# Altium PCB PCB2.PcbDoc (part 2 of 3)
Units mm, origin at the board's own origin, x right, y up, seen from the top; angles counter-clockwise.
Board outline 277.37 x 238.38 mm, 2 copper layers (Top Layer, Bottom Layer); 139 components, 149 nets, 593 pads, 86 vias.
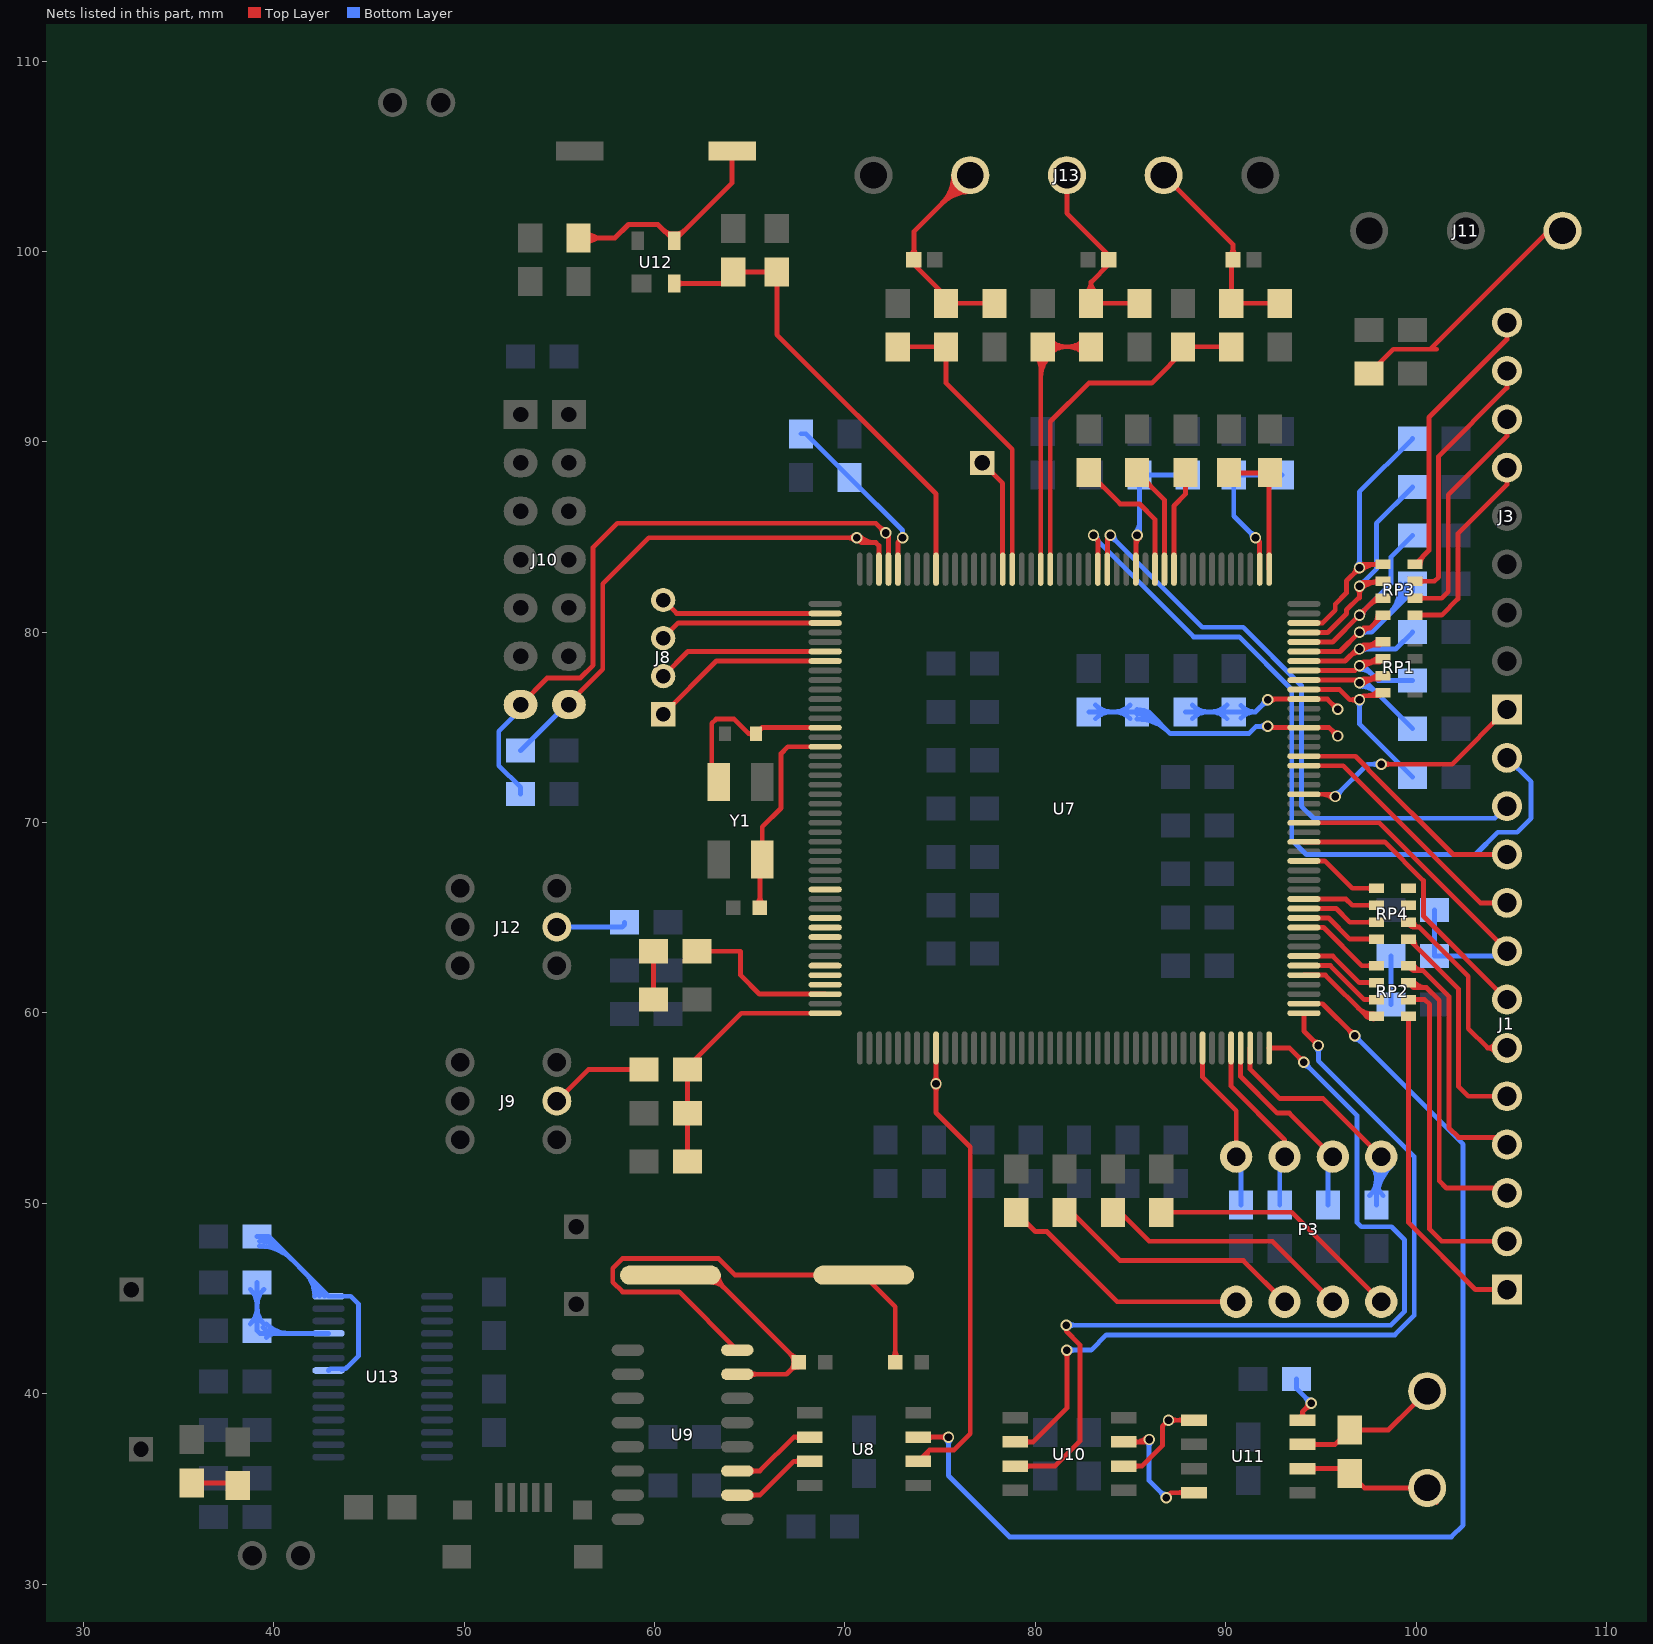
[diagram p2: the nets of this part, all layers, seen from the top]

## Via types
v1: diameter 0.6, hole 0.4, Top Layer to Bottom Layer, 86 vias

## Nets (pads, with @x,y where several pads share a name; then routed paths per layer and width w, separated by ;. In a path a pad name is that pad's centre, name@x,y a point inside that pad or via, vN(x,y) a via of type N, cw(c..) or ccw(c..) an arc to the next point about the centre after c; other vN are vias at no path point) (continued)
A0: C32.2 RP3.5 U7.42 | length 19.1
  Top Layer w0.254: U7.42@94.109,80.489 95.094,80.489 95.758,81.153 95.758,81.481 96.347,82.07 96.347,82.705 96.954,83.312 v1@97.028,83.312 ; v1(97.028,83.386) 97.208,83.566 RP3.5@98.26,83.566 ; 96.733,83.091 cw(c97.028,82.795) 97.028,83.213 ccw(c97.028,82.795) 96.733,83.091 ; 96.733,83.091 ccw(c96.437,83.386) 96.855,83.386 cw(c96.437,83.386) 96.733,83.091 ; 97.813,83.566 cw(c97.813,83.269) 98.023,83.479 ccw(c97.813,83.269) 97.813,83.566 ; 97.813,83.566 ccw(c97.813,83.863) 98.023,83.653 cw(c97.813,83.863) 97.813,83.566 ; v1@97.15,83.264 cw(c97.88,82.534) 97.88,83.566 ccw(c97.88,82.534) v1@97.15,83.264
  Bottom Layer w0.254: v1(97.028,83.386) 97.028,87.376 C32.2@99.822,90.17 ; 97.028,83.804 cw(c96.61,83.804) 96.906,83.508 ccw(c96.61,83.804) 97.028,83.804 ; 97.028,83.804 ccw(c97.446,83.804) 97.15,83.508 cw(c97.446,83.804) 97.028,83.804
A1: C31.2 RP3.6 U7.41 | length 18.3
  Top Layer w0.254: U7.41@94.109,79.989 95.356,79.989 96.347,80.98 96.347,81.181 96.954,81.788 97.028,81.788 v1(97.028,82.423) 97.236,82.631 RP3.6@98.214,82.631 ; RP3.6@97.956,82.631 RP3.6@98.214,82.631 ; RP3.6@98.26,82.677 RP3.6@98.214,82.631 ; 97.028,82.005 cw(c97.446,82.005) v1@97.15,82.301 ; 97.028,82.005 ccw(c96.61,82.005) 96.906,82.301 cw(c96.61,82.005) 97.028,82.005 ; 97.028,82.005 cw(c97.446,82.005) v1@97.15,82.301 ; v1@97.15,82.301 cw(c97.948,81.503) 97.948,82.631 ccw(c97.948,81.503) v1@97.15,82.301 ; v1@96.971,82.48 cw(c97.335,82.116) 97.335,82.631 ccw(c97.335,82.116) v1@96.971,82.48 ; 97.702,82.631 ccw(c97.702,83.085) 98.023,82.764 cw(c97.702,83.085) 97.702,82.631
  Bottom Layer w0.254: v1(97.028,82.423) 97.917,83.312 97.917,85.725 C31.2@99.822,87.63 ; 97.323,82.718 cw(c97.028,83.014) 97.028,82.596 ccw(c97.028,83.014) 97.323,82.718 ; 97.323,82.718 ccw(c97.619,82.423) 97.201,82.423 cw(c97.619,82.423) 97.323,82.718
A2: C30.2 RP3.7 U7.40 | length 14.3
  Top Layer w0.254: U7.40@94.109,79.489 95.618,79.489 v1(97.028,80.899) 97.917,81.788 RP3.7@98.26,81.788 ; 97.323,81.194 cw(c97.028,81.49) 97.028,81.072 ccw(c97.028,81.49) 97.323,81.194 ; 97.323,81.194 ccw(c97.619,80.899) 97.201,80.899 cw(c97.619,80.899) 97.323,81.194 ; 97.571,81.442 cw(c98.11,80.902) 98.11,81.665 ccw(c98.11,80.902) 97.571,81.442
  Bottom Layer w0.254: v1(97.028,80.899) 98.679,82.55 98.679,83.947 C30.2@99.822,85.09 ; 97.323,81.194 cw(c97.028,81.49) 97.028,81.072 ccw(c97.028,81.49) 97.323,81.194 ; 97.323,81.194 ccw(c97.619,80.899) 97.201,80.899 cw(c97.619,80.899) 97.323,81.194
A3: C29.2 RP3.8 U7.39 | length 21
  Top Layer w0.254: U7.39@94.109,78.989 96.007,78.989 v1(97.028,80.01) 97.236,80.218 97.579,80.218 ; RP3.8@98.26,80.899 97.579,80.218 ; 97.579,80.218 ccw(c97.579,79.802) 97.19,79.949 cw(c97.579,79.802) 97.579,80.218 ; 97.794,80.433 ccw(c97.328,80.899) 97.987,80.899 cw(c97.328,80.899) 97.794,80.433
  Bottom Layer w0.254: v1(97.028,80.01) 97.663,80.01 99.822,82.169 C29.2@99.822,82.55 ; 97.446,80.01 cw(c97.446,80.428) 97.15,80.132 ccw(c97.446,80.428) 97.446,80.01 ; 97.446,80.01 ccw(c97.446,79.592) 97.15,79.888 cw(c97.446,79.592) 97.446,80.01 ; 98.469,80.816 ccw(c96.734,82.55) 99.187,82.55 cw(c96.734,82.55) 98.469,80.816 ; 98.902,81.249 ccw(c97.601,82.55) 99.441,82.55 cw(c97.601,82.55) 98.902,81.249 ; 99.336,81.683 ccw(c98.469,82.55) 99.695,82.55 cw(c98.469,82.55) 99.336,81.683
A4: C28.2 RP1.5 U7.38 | length 14.2
  Top Layer w0.254: U7.38@94.109,78.489 96.269,78.489 96.901,79.121 v1(97.028,79.121) 97.236,79.329 98.087,79.329 RP1.5@98.26,79.502 ; 96.516,78.736 cw(c97.028,78.224) 97.028,78.948 ccw(c97.028,78.224) 96.516,78.736 ; v1@96.971,79.178 cw(c97.335,78.814) 97.335,79.329 ccw(c97.335,78.814) v1@96.971,79.178 ; v1@97.15,78.999 cw(c97.948,78.201) 97.948,79.329 ccw(c97.948,78.201) v1@97.15,78.999 ; 97.395,79.329 ccw(c97.395,80.217) 98.023,79.589 cw(c97.395,80.217) 97.395,79.329
  Bottom Layer w0.254: v1(97.028,79.121) 98.933,79.121 C28.2@99.822,80.01 ; 97.446,79.121 cw(c97.446,79.539) 97.15,79.243 ccw(c97.446,79.539) 97.446,79.121 ; 97.446,79.121 ccw(c97.446,78.703) 97.15,78.999 cw(c97.446,78.703) 97.446,79.121
A5: C27.1 RP1.6 U7.37 | length 12.3
  Top Layer w0.254: U7.37@94.109,77.989 96.785,77.989 ; v1@97.236,78.44 98.087,78.44 RP1.6@98.26,78.613 ; v1@96.971,78.289 cw(c97.335,77.925) 97.335,78.44 ccw(c97.335,77.925) v1@96.971,78.289 ; v1@97.15,78.11 cw(c97.948,77.312) 97.948,78.44 ccw(c97.948,77.312) v1@97.15,78.11 ; 97.395,78.44 ccw(c97.395,79.328) 98.023,78.7 cw(c97.395,79.328) 97.395,78.44
  Bottom Layer w0.254: v1(97.028,78.232) 97.238,78.232 98,77.47 C27.1@99.822,77.47 ; v1@97.028,78.059 cw(c97.028,77.133) 97.683,77.788 ccw(c97.028,77.133) v1@97.028,78.059
A6: C26.2 RP1.7 U7.36 | length 15.2
  Top Layer w0.254: U7.36@94.109,77.489 v1@96.882,77.489 ; v1(97.028,77.343) 97.236,77.551 98.087,77.551 RP1.7@98.26,77.724 ; v1@96.971,77.4 cw(c97.335,77.036) 97.335,77.551 ccw(c97.335,77.036) v1@96.971,77.4 ; v1@97.15,77.221 cw(c97.948,76.423) 97.948,77.551 ccw(c97.948,76.423) v1@97.15,77.221 ; 97.395,77.551 ccw(c97.395,78.439) 98.023,77.811 cw(c97.395,78.439) 97.395,77.551
  Bottom Layer w0.254: v1(97.028,77.343) 97.409,77.343 C26.2@99.822,74.93 ; v1@97.028,77.17 cw(c97.028,75.833) 97.974,76.778 ccw(c97.028,75.833) v1@97.028,77.17 ; v1@97.028,77.424 cw(c97.028,76.7) 97.54,77.212 ccw(c97.028,76.7) v1@97.028,77.424
A7: C25.2 RP1.8 U7.35 | length 13.8
  Top Layer w0.254: U7.35@94.109,76.989 95.985,76.989 96.52,76.454 v1(97.028,76.454) 97.236,76.662 98.087,76.662 RP1.8@98.26,76.835 ; 96.61,76.454 cw(c96.61,76.036) 96.906,76.332 ccw(c96.61,76.036) 96.61,76.454 ; 96.61,76.454 ccw(c96.61,76.872) 96.906,76.576 cw(c96.61,76.872) 96.61,76.454 ; 97.395,76.662 ccw(c97.395,77.55) 98.023,76.922 cw(c97.395,77.55) 97.395,76.662
  Bottom Layer w0.254: v1(97.028,76.454) 97.028,75.184 C25.2@99.822,72.39 ; 97.028,76.036 cw(c97.446,76.036) 97.15,76.332 ccw(c97.446,76.036) 97.028,76.036 ; 97.028,76.036 ccw(c96.61,76.036) 96.906,76.332 cw(c96.61,76.036) 97.028,76.036
A_FB: J3.7 RP3.2 | length 13.1
  Top Layer w0.254: RP3.2@99.949,81.788 101.346,81.788 101.693,82.135 101.693,87.216 104.775,90.298 J3.7@104.775,91.186 ; 100.396,81.788 cw(c100.396,82.085) 100.186,81.875 ccw(c100.396,82.085) 100.396,81.788 ; 100.396,81.788 ccw(c100.396,81.491) 100.186,81.701 cw(c100.396,81.491) 100.396,81.788
B0: C33.2 R23.2 U7.46 | length 9.4
  Top Layer w0.254: v1(91.567,84.963) 91.784,84.746 U7.46@91.784,83.314
  Bottom Layer w0.254: v1(91.567,84.963) 90.424,86.106 R23.2@90.424,88.265 C33.2@92.964,88.265 ; 91.272,85.258 cw(c90.976,84.963) 91.394,84.963 ccw(c90.976,84.963) 91.272,85.258 ; 91.272,85.258 ccw(c91.567,85.554) 91.567,85.136 cw(c91.567,85.554) 91.272,85.258
B_FB: J3.8 RP3.3 | length 14.6
  Top Layer w0.254: RP3.3@99.949,82.677 100.965,82.677 101.185,82.897 101.185,89.248 104.775,92.838 J3.8@104.775,93.726 ; 100.396,82.677 cw(c100.396,82.974) 100.186,82.764 ccw(c100.396,82.974) 100.396,82.677 ; 100.396,82.677 ccw(c100.396,82.38) 100.186,82.59 cw(c100.396,82.38) 100.396,82.677
C_FB: J3.9 RP3.4 | length 15.7
  Top Layer w0.254: RP3.4@99.949,83.566 100.677,84.294 100.677,91.28 104.775,95.378 J3.9@104.775,96.266 ; RP3.4@100.222,83.566 cw(c100.881,83.566) 100.415,84.032 ccw(c100.881,83.566) RP3.4@100.222,83.566
CANRXA: U7.1 U10.2 | length 50.4
  Top Layer w0.254: U10.2@78.938,37.465 79.883,37.465 81.661,39.243 v1(81.661,42.291) ; U7.1@94.109,59.989 94.109,59.053 v1(94.869,58.293) ; 79.731,37.465 cw(c79.731,37.883) 79.435,37.587 ccw(c79.731,37.883) 79.731,37.465 ; 79.731,37.465 ccw(c79.731,37.047) 79.435,37.343 cw(c79.731,37.047) 79.731,37.465 ; 81.661,41.873 cw(c82.079,41.873) 81.783,42.169 ccw(c82.079,41.873) 81.661,41.873 ; 81.661,41.873 ccw(c81.243,41.873) 81.539,42.169 cw(c81.243,41.873) 81.661,41.873 ; 94.574,58.588 cw(c94.278,58.293) 94.696,58.293 ccw(c94.278,58.293) 94.574,58.588 ; 94.574,58.588 ccw(c94.869,58.884) 94.869,58.466 cw(c94.869,58.884) 94.574,58.588
  Bottom Layer w0.254: v1(81.661,42.291) 82.931,42.291 83.732,43.092 98.891,43.092 99.91,44.111 99.91,52.453 94.869,57.494 v1(94.869,58.293) ; 82.079,42.291 cw(c82.079,42.709) 81.783,42.413 ccw(c82.079,42.709) 82.079,42.291 ; 82.079,42.291 ccw(c82.079,41.873) 81.783,42.169 cw(c82.079,41.873) 82.079,42.291 ; 94.869,57.875 cw(c95.287,57.875) 94.991,58.171 ccw(c95.287,57.875) 94.869,57.875 ; 94.869,57.875 ccw(c94.451,57.875) 94.747,58.171 cw(c94.451,57.875) 94.869,57.875
CANTXA: U7.176 U10.3 | length 52
  Top Layer w0.254: U10.3@78.938,36.195 81.026,36.195 82.342,37.511 82.342,42.573 81.622,43.293 v1(81.622,43.6) ; U7.176@92.284,58.164 93.347,58.164 v1(94.107,57.404) ; 79.731,36.195 cw(c79.731,36.613) 79.435,36.317 ccw(c79.731,36.613) 79.731,36.195 ; 79.731,36.195 ccw(c79.731,35.777) 79.435,36.073 cw(c79.731,35.777) 79.731,36.195 ; 93.812,57.699 cw(c93.516,57.404) 93.934,57.404 ccw(c93.516,57.404) 93.812,57.699 ; 93.812,57.699 ccw(c94.107,57.995) 94.107,57.577 cw(c94.107,57.995) 93.812,57.699
  Bottom Layer w0.254: v1(81.622,43.6) 98.681,43.6 99.402,44.321 99.402,48.076 98.71,48.768 97.124,48.768 96.901,48.991 96.901,54.61 v1(94.107,57.404) ; 82.04,43.6 cw(c82.04,44.018) 81.744,43.722 ccw(c82.04,44.018) 82.04,43.6 ; 82.04,43.6 ccw(c82.04,43.182) 81.744,43.478 cw(c82.04,43.182) 82.04,43.6 ; 94.402,57.109 cw(c94.698,57.404) 94.28,57.404 ccw(c94.698,57.404) 94.402,57.109 ; 94.402,57.109 ccw(c94.107,56.813) 94.107,57.231 cw(c94.107,56.813) 94.402,57.109
DC_FB: J3.6 RP3.1 | length 11.5
  Top Layer w0.254: RP3.1@99.949,80.899 101.346,80.899 102.201,81.754 102.201,85.184 104.775,87.758 J3.6@104.775,88.646 ; 100.396,80.899 cw(c100.396,81.196) 100.186,80.986 ccw(c100.396,81.196) 100.396,80.899 ; 100.396,80.899 ccw(c100.396,80.602) 100.186,80.812 cw(c100.396,80.602) 100.396,80.899
DIR: C49.2 R27.2 R33.2 U7.132 | length 13.4
  Top Layer w0.254: C49.2@61.722,52.197 R33.2@61.722,54.737 R27.2@61.722,57.023 61.722,57.15 64.561,59.989 U7.132@68.959,59.989
EMU0: J10.13 R36.2 U7.85 | length 35.7
  Top Layer w0.254: J10.13@52.959,76.2 54.356,77.597 56.099,77.597 56.769,78.267 56.769,84.455 58.039,85.725 71.628,85.725 v1(72.136,85.217) ; U7.85@72.284,83.314 v1@72.284,85.069 ; 71.841,85.512 cw(c71.545,85.217) 71.963,85.217 ccw(c71.545,85.217) 71.841,85.512 ; 71.841,85.512 ccw(c72.136,85.808) 72.136,85.39 cw(c72.136,85.808) 71.841,85.512
  Bottom Layer w0.254: R36.2@52.959,71.501 52.959,71.851 51.816,72.994 51.816,74.803 52.959,75.946 J10.13@52.959,76.2
EMU1: J10.14 R37.1 U7.86 | length 31.8
  Top Layer w0.254: J10.14@55.499,76.2 55.499,76.278 57.277,78.056 57.277,82.55 59.69,84.963 v1(70.612,84.963) 70.866,84.709 71.628,84.709 ; U7.86@71.784,83.314 71.784,84.553 71.628,84.709 ; 70.194,84.963 cw(c70.194,84.545) 70.49,84.841 ccw(c70.194,84.545) 70.194,84.963 ; 70.194,84.963 ccw(c70.194,85.381) 70.49,85.085 cw(c70.194,85.381) 70.194,84.963 ; 71.628,84.709 cw(c71.628,85.958) 70.736,85.084 ccw(c71.628,85.958) 71.628,84.709 ; v1@70.554,84.906 ccw(c71.024,85.366) 71.024,84.709 cw(c71.024,85.366) v1@70.554,84.906
  Bottom Layer w0.254: R37.1@52.959,73.787 J10.14@55.372,76.2
EN_GATE: J1.7 U7.19 | length 15.2
  Top Layer w0.254: U7.19@94.109,68.989 98.354,68.989 100.387,66.956 100.387,65.094 J1.7@104.775,60.706
GHA: 
GHB: 
GHC: 
GLA: 
GLB: 
GLC: 
GPIO66: U7.119
GPIO67: U7.122
GPIO68: U7.123
GPIO69: U7.124
GPIO70: U7.127
GPIO71: U7.128
GPIO72: U7.129
GPIO84: P3.1 R38.2 U7.169 | length 8.7
  Top Layer w0.254: U7.169@88.784,58.164 88.784,56.631 90.551,54.864 P3.1@90.551,52.451
  Bottom Layer w0.254: R38.2@90.805,49.911 P3.1@90.805,52.197
GPIO85: P3.2 R39.2 U7.172 | length 9.2
  Top Layer w0.254: U7.172@90.284,58.164 90.284,56.147 93.091,53.34 P3.2@93.091,52.451
  Bottom Layer w0.254: R39.2@92.837,49.911 P3.2@92.837,52.197
GPIO86: P3.3 R40.2 U7.173 | length 10.4
  Top Layer w0.254: U7.173@90.784,58.164 90.784,56.663 92.71,54.737 93.345,54.737 P3.3@95.631,52.451
  Bottom Layer w0.254: R40.2@95.377,49.911 P3.3@95.377,52.197
GPIO87: P3.4 R41.2 U7.174 | length 26.8
  Top Layer w0.254: U7.174@91.284,58.164 91.284,57.052 92.837,55.499 95.123,55.499 P3.4@98.171,52.451
  Bottom Layer w0.254: R41.2@97.917,49.911 P3.4@97.917,52.197 ; 97.917,51.264 cw(c96.691,51.264) 97.558,50.397 ccw(c96.691,51.264) 97.917,51.264 ; 97.917,51.264 ccw(c99.143,51.264) 98.276,50.397 cw(c99.143,51.264) 97.917,51.264 ; 97.917,51.319 cw(c99.303,51.319) 98.323,52.299 ccw(c99.303,51.319) 97.917,51.319 ; 97.917,51.319 ccw(c97.039,51.319) 97.66,51.94 cw(c97.039,51.319) 97.917,51.319 ; R41.2@97.917,50.092 cw(c100.53,50.092) 98.682,51.94 ccw(c100.53,50.092) R41.2@97.917,50.092 ; 97.917,50.706 cw(c99.916,50.706) 98.503,52.119 ccw(c99.916,50.706) 97.917,50.706
HALLA: C63.2 R54.2 U7.68 | length 19.1
  Top Layer w0.254: U7.68@80.784,83.314 80.784,91.071 82.804,93.091 86.106,93.091 C63.2@88.011,94.996 ; C63.2@87.757,94.996 C63.2@88.011,94.996 ; R54.2@90.297,94.996 C63.2@88.011,94.996
HALLB: C62.2 R53.2 U7.69 | length 27.2
  Top Layer w0.254: U7.69@80.284,83.314 80.284,88.138 C62.2@80.284,94.889 ; C62.2@80.391,94.996 R53.2@82.931,94.996 ; 81.617,94.996 cw(c81.617,96.222) 80.75,95.355 ccw(c81.617,96.222) 81.617,94.996 ; 81.617,94.996 ccw(c81.617,93.77) 80.75,94.637 cw(c81.617,93.77) 81.617,94.996 ; 81.705,94.996 cw(c81.705,93.77) 82.572,94.637 ccw(c81.705,93.77) 81.705,94.996 ; 81.705,94.996 ccw(c81.705,96.222) 82.572,95.355 cw(c81.705,96.222) 81.705,94.996 ; C62.2@80.032,94.51 cw(c79.423,93.901) 80.284,93.901 ccw(c79.423,93.901) C62.2@80.032,94.51 ; 80.284,93.384 cw(c81.876,93.384) 80.75,94.51 ccw(c81.876,93.384) 80.284,93.384 ; 80.284,93.997 cw(c81.263,93.997) 80.571,94.689 ccw(c81.263,93.997) 80.284,93.997
HALLC: C61.2 R52.2 U7.72 | length 15.7
  Top Layer w0.254: C61.2@72.771,94.996 R52.2@75.311,94.996 75.311,93.091 78.784,89.618 U7.72@78.784,83.314
INHA: J1.6 RP4.6 | length 13.3
  Top Layer w0.254: RP4.6@99.606,64.77 99.864,64.512 100.164,64.512 ; J1.6@104.775,58.166 103.759,58.166 ; 100.164,64.512 cw(c100.164,64.798) 99.879,64.778 ccw(c100.164,64.798) 100.164,64.512 ; 100.164,64.512 102.743,61.933 102.743,59.182 103.759,58.166 ; 103.759,58.166 cw(c103.759,57.715) 104.171,57.898 ccw(c103.759,57.715) 103.759,58.166 ; 103.759,58.166 ccw(c103.759,58.617) 104.171,58.434 cw(c103.759,58.617) 103.759,58.166 ; RP4.6@99.625,64.761 ccw(c99.892,64.779) 99.892,64.512 cw(c99.892,64.779) RP4.6@99.625,64.761
INHB: J1.4 RP2.8 | length 15.2
  Top Layer w0.254: RP2.8@99.606,62.484 99.864,62.226 100.374,62.226 ; J1.4@104.775,53.086 104.394,53.467 102.235,53.467 101.727,53.975 101.727,60.873 100.374,62.226 ; 100.374,62.226 cw(c100.374,62.794) 99.866,62.539 ccw(c100.374,62.794) 100.374,62.226 ; RP2.8@99.639,62.425 ccw(c99.962,62.587) 99.962,62.226 cw(c99.962,62.587) RP2.8@99.639,62.425
INHC: J1.2 RP2.6 | length 18.3
  Top Layer w0.254: RP2.6@99.606,60.706 100.457,60.706 100.711,60.452 100.711,48.641 101.346,48.006 J1.2@104.775,48.006 ; 100.053,60.706 cw(c100.053,61.003) 99.843,60.793 ccw(c100.053,61.003) 100.053,60.706 ; 100.053,60.706 ccw(c100.053,60.409) 99.843,60.619 cw(c100.053,60.409) 100.053,60.706
INLA: J1.5 RP4.5 | length 12.6
  Top Layer w0.254: RP4.5@99.606,63.881 102.235,61.252 102.235,56.134 102.743,55.626 J1.5@104.775,55.626 ; RP4.5@99.879,63.881 ccw(c100.538,63.881) 100.072,63.415 cw(c100.538,63.881) RP4.5@99.879,63.881
INLB: J1.3 RP2.7 | length 17.7
  Top Layer w0.254: RP2.7@99.606,61.595 99.864,61.337 100.544,61.337 ; J1.3@104.775,50.546 104.521,50.8 101.6,50.8 101.219,51.181 101.219,60.662 100.544,61.337 ; 100.544,61.337 cw(c100.544,62.22) 99.852,61.671 ccw(c100.544,62.22) 100.544,61.337 ; RP2.7@99.653,61.514 ccw(c100.019,61.803) 100.019,61.337 cw(c100.019,61.803) RP2.7@99.653,61.514
INLC: J1.1 RP2.5 | length 18.4
  Top Layer w0.254: RP2.5@99.606,59.817 99.606,48.984 103.124,45.466 J1.1@104.775,45.466 ; 99.606,59.52 cw(c99.903,59.52) 99.693,59.73 ccw(c99.903,59.52) 99.606,59.52 ; 99.606,59.52 ccw(c99.309,59.52) 99.519,59.73 cw(c99.309,59.52) 99.606,59.52
LED: R58.1 U7.130 | length 8.4
  Top Layer w0.254: R58.1@62.23,63.246 64.516,63.246 64.516,61.984 65.503,60.997 ; 65.503,60.989 U7.130@68.959,60.989
Net6_1: 6.1 U7.73 | length 6
  Top Layer w0.254: 6.1@77.216,88.9 78.284,87.832 U7.73@78.284,83.314
NetC3_2: 
NetC4_2: 
NetC5_2: 
NetC6_2: 
NetC7_1: 
NetC7_2: 
NetC9_1: 
NetC9_2: 
NetC14_1: 
NetC34_1: C34.1 L1.2 U7.31 | length 32.3
  Top Layer w0.254: v1@92.397,74.989 U7.31@94.109,74.989 95.445,74.989 v1(95.885,74.549) ; 95.59,74.844 cw(c95.294,74.549) 95.712,74.549 ccw(c95.294,74.549) 95.59,74.844 ; 95.59,74.844 ccw(c95.885,75.14) 95.885,74.722 cw(c95.885,75.14) 95.59,74.844
  Bottom Layer w0.254: L1.2@82.804,75.819 C34.1@85.344,75.819 85.948,75.819 87.091,74.676 91.217,74.676 91.598,75.057 v1(92.202,75.057) ; 84.03,75.819 cw(c84.03,77.045) 83.163,76.178 ccw(c84.03,77.045) 84.03,75.819 ; 84.03,75.819 ccw(c84.03,74.593) 83.163,75.46 cw(c84.03,74.593) 84.03,75.819 ; 84.118,75.819 cw(c84.118,74.593) 84.985,75.46 ccw(c84.118,74.593) 84.118,75.819 ; 84.118,75.819 ccw(c84.118,77.045) 84.985,76.178 cw(c84.118,77.045) 84.118,75.819 ; 91.784,75.057 cw(c91.784,74.639) 92.08,74.935 ccw(c91.784,74.639) 91.784,75.057 ; 91.784,75.057 ccw(c91.784,75.475) 92.08,75.179 cw(c91.784,75.475) 91.784,75.057 ; C34.1@85.344,75.438 cw(c85.347,73.067) 87.024,74.743 ccw(c85.347,73.067) C34.1@85.344,75.438 ; C34.1@85.344,75.692 cw(c85.346,73.932) 86.591,75.176 ccw(c85.346,73.932) C34.1@85.344,75.692 ; C34.1@85.344,75.946 cw(c85.345,74.796) 86.158,75.609 ccw(c85.345,74.796) C34.1@85.344,75.946
NetC38_2: C38.2 L2.2 U7.34 | length 23.5
  Top Layer w0.254: v1@92.075,76.454 v1(92.202,76.454) ; v1@92.421,76.489 U7.34@94.109,76.489 95.342,76.489 v1(95.885,75.946) ; 95.59,76.241 cw(c95.294,75.946) 95.712,75.946 ccw(c95.294,75.946) 95.59,76.241 ; 95.59,76.241 ccw(c95.885,76.537) 95.885,76.119 cw(c95.885,76.537) 95.59,76.241 ; v1@92.324,76.332 cw(c92.704,75.952) 92.704,76.489 ccw(c92.704,75.952) v1@92.324,76.332 ; v1@92.324,76.576 ccw(c92.535,76.787) 92.535,76.489 cw(c92.535,76.787) v1@92.324,76.576
  Bottom Layer w0.254: L2.2@87.884,75.819 C38.2@90.424,75.819 91.567,75.819 ; v1(92.202,76.454) 91.567,75.819 ; 89.11,75.819 cw(c89.11,77.045) 88.243,76.178 ccw(c89.11,77.045) 89.11,75.819 ; 89.11,75.819 ccw(c89.11,74.593) 88.243,75.46 cw(c89.11,74.593) 89.11,75.819 ; 89.198,75.819 cw(c89.198,74.593) 90.065,75.46 ccw(c89.198,74.593) 89.198,75.819 ; 89.198,75.819 ccw(c89.198,77.045) 90.065,76.178 cw(c89.198,77.045) 89.198,75.819 ; 91.567,75.819 cw(c91.567,76.851) 90.801,76.159 ccw(c91.567,76.851) 91.567,75.819 ; 91.567,75.819 ccw(c91.567,74.787) 90.801,75.479 cw(c91.567,74.787) 91.567,75.819 ; 91.907,76.159 cw(c92.202,75.863) 92.202,76.281 ccw(c92.202,75.863) 91.907,76.159 ; 91.907,76.159 ccw(c91.611,76.454) 92.029,76.454 cw(c91.611,76.454) 91.907,76.159
NetC39_1: C39.1 U7.104 Y1.3 | length 12.8
  Top Layer w0.254: C39.1@65.532,65.532 Y1.3@65.532,67.945 ; Y1.3@65.659,68.072 65.659,69.774 66.64,70.755 66.64,73.625 67.004,73.989 U7.104@68.959,73.989 ; 65.532,66.145 cw(c64.919,66.145) 65.352,65.712 ccw(c64.919,66.145) 65.532,66.145 ; 65.532,66.145 ccw(c66.145,66.145) 65.712,65.712 cw(c66.145,66.145) 65.532,66.145
NetC40_1: C40.1 U7.102 Y1.1 | length 10.8
  Top Layer w0.254: Y1.1@63.373,72.136 63.005,72.504 63.005,75.215 63.228,75.438 64.179,75.438 64.941,74.676 ; U7.102@68.959,74.989 65.642,74.989 C40.1@65.329,74.676 64.941,74.676 ; 64.941,74.676 cw(c64.941,74.376) 65.178,74.559 ccw(c64.941,74.376) 64.941,74.676 ; 64.941,74.676 ccw(c64.941,74.976) 65.178,74.793 cw(c64.941,74.976) 64.941,74.676
NetC41_2: C41.2 U9.7 Y2.1 | length 20.1
  Top Layer w0.254: Y2.1@60.833,46.228 62.992,46.228 C41.2@67.564,41.656 66.929,41.021 U9.7@64.343,41.021 ; 65.311,41.021 cw(c65.311,41.439) 65.015,41.143 ccw(c65.311,41.439) 65.311,41.021 ; 65.311,41.021 ccw(c65.311,40.603) 65.015,40.899 cw(c65.311,40.603) 65.311,41.021 ; 67.13,41.222 cw(c67.564,40.789) 67.564,41.402 ccw(c67.564,40.789) 67.13,41.222 ; 67.13,41.222 ccw(c66.697,41.656) C41.2@67.31,41.656 ; 67.13,41.222 ccw(c66.697,41.656) C41.2@67.31,41.656 ; 67.13,42.09 cw(c66.697,41.656) C41.2@67.31,41.656 ; 67.13,42.09 ccw(c67.564,42.523) 67.564,41.91 cw(c67.564,42.523) 67.13,42.09 ; 67.13,42.09 cw(c66.697,41.656) C41.2@67.31,41.656 ; Y2.1@62.983,45.855 cw(c62.983,44.933) 63.635,45.585 ccw(c62.983,44.933) Y2.1@62.983,45.855 ; Y2.1@63.356,46.228 ccw(c64.235,46.228) 63.613,45.607 cw(c64.235,46.228) Y2.1@63.356,46.228
NetC42_2: C42.2 U9.8 Y2.3 | length 29.7
  Top Layer w0.254: U9.8@64.343,42.291 61.287,45.347 58.318,45.347 57.802,45.863 57.802,46.593 58.318,47.109 63.348,47.109 64.229,46.228 Y2.3@70.983,46.228 72.644,44.567 C42.2@72.644,41.656 ; 72.644,42.269 cw(c72.031,42.269) 72.464,41.836 ccw(c72.031,42.269) 72.644,42.269 ; 72.644,42.269 ccw(c73.257,42.269) 72.824,41.836 cw(c73.257,42.269) 72.644,42.269
NetC44_2: C44.2 L4.2 U7.59 | length 9.8
  Top Layer w0.254: U7.59@85.284,83.314 v1@85.284,85.03 ; 85.284,84.527 cw(c85.907,84.527) 85.466,84.968 ccw(c85.907,84.527) 85.284,84.527
  Bottom Layer w0.254: v1(85.344,85.09) 85.471,85.217 C44.2@85.471,88.265 L4.2@88.011,88.265 ; v1@85.222,85.212 ccw(c84.62,85.814) 85.471,85.814 cw(c84.62,85.814) v1@85.222,85.212
NetC45_1: C45.1 L5.2 U7.84 | length 9.6
  Top Layer w0.254: U7.84@72.784,83.314 72.784,84.722 v1(73.025,84.963)
  Bottom Layer w0.254: L5.2@67.691,90.424 67.945,90.424 C45.1@70.231,88.138 73.025,85.344 v1(73.025,84.963)
NetC48_2: C48.2 L3.2 U7.45 | length 7.3
  Top Layer w0.254: C48.2@90.043,88.367 L3.2@92.202,88.367 ; U7.45@92.284,83.314 L3.2@92.284,88.474
NetD2_2: 
NetD7_K: D7.2 R57.2 | length 2.5
  Bottom Layer w0.254: D7.2@98.679,60.452 R57.2@98.679,62.992
NetD8_K: D8.2 R58.2 | length 2.5
  Top Layer w0.254: D8.2@59.944,60.706 R58.2@59.944,63.246
NetD12_A: D12.1 R56.1 | length 2.5
  Top Layer w0.254: R56.1@35.687,35.306 37.973,35.306 D12.1@38.1,35.179
NetJ2_1: 
NetJ6_7: RP4.7
NetJ6_8: RP4.8
NetJ8_1: J8.1 U7.95 | length 9.7
  Top Layer w0.254: J8.1@60.452,75.692 63.249,78.489 U7.95@68.959,78.489
NetJ8_2: J8.2 U7.94 | length 9
  Top Layer w0.254: J8.2@60.452,77.692 61.749,78.989 U7.94@68.959,78.989
NetJ8_3: J8.3 U7.91 | length 8.8
  Top Layer w0.254: J8.3@60.452,79.692 61.249,80.489 U7.91@68.959,80.489
NetJ8_4: J8.4 U7.90 | length 8.8
  Top Layer w0.254: J8.4@60.452,81.692 61.155,80.989 U7.90@68.959,80.989
NetJ9_2: J9.2 R27.1 | length 4.7
  Top Layer w0.254: J9.2@55.245,55.753 56.515,57.023 R27.1@59.436,57.023
NetJ11_3: J11.3 R42.1 | length 13.6
  Top Layer w0.254: R42.1@97.536,93.599 98.806,94.869 100.711,94.869 100.742,94.869 ; 101.092,94.869 100.742,94.869 ; J11.3@107.696,101.092 106.965,101.092 100.742,94.869
NetJ12_2: J12.2 R44.1 | length 3.7
  Bottom Layer w0.254: J12.2@54.864,64.516 58.293,64.516 58.42,64.643 R44.1@58.42,64.77
NetP2_1: P2.1 R26.2 U11.7 | length 9
  Top Layer w0.254: U11.7@94.036,37.338 95.758,37.338 R26.2@96.52,38.1 98.552,38.1 99.822,39.37 P2.1@100.584,40.132 ; 94.829,37.338 cw(c94.829,37.756) 94.533,37.46 ccw(c94.829,37.756) 94.829,37.338 ; 94.829,37.338 ccw(c94.829,36.92) 94.533,37.216 cw(c94.829,36.92) 94.829,37.338
NetP2_2: P2.2 R26.1 U11.6 | length 8.7
  Top Layer w0.254: U11.6@94.036,36.068 R26.1@96.266,36.068 ; R26.1@96.52,35.814 97.282,35.052 100.33,35.052 P2.2@101.092,34.29 ; 94.829,36.068 cw(c94.829,36.486) 94.533,36.19 ccw(c94.829,36.486) 94.829,36.068 ; 94.829,36.068 ccw(c94.829,35.65) 94.533,35.946 cw(c94.829,35.65) 94.829,36.068
NetP3_5: P3.5 R29.1 | length 13.5
  Top Layer w0.254: R29.1@86.614,49.53 93.472,49.53 P3.5@98.171,44.831
NetP3_6: P3.6 R30.1 | length 13.5
  Top Layer w0.254: R30.1@84.074,49.53 84.455,49.53 85.979,48.006 92.456,48.006 P3.6@95.631,44.831
NetP3_7: P3.7 R31.1 | length 13.5
  Top Layer w0.254: R31.1@81.534,49.53 81.915,49.53 84.455,46.99 90.932,46.99 P3.7@93.091,44.831
NetP3_8: P3.8 R32.1 | length 13.5
  Top Layer w0.254: R32.1@78.994,49.53 80.01,48.514 80.614,48.514 84.297,44.831 P3.8@90.551,44.831
NetR6_2: 
NetR7_2: 
NetR9_2: 
NetR10_2: 
NetR25_2: R25.2 U11.8 | length 6.6
  Top Layer w0.254: U11.8@94.036,38.608 94.036,39.045 v1(94.488,39.497) ; 94.036,39.026 cw(c93.618,39.026) 93.914,38.73 ccw(c93.618,39.026) 94.036,39.026 ; 94.036,39.026 ccw(c94.454,39.026) 94.158,38.73 cw(c94.454,39.026) 94.036,39.026 ; 94.193,39.202 cw(c94.488,38.906) 94.488,39.324 ccw(c94.488,38.906) 94.193,39.202 ; 94.193,39.202 ccw(c93.897,39.497) 94.315,39.497 cw(c93.897,39.497) 94.193,39.202
  Bottom Layer w0.254: R25.2@93.726,40.767 93.726,40.259 v1(94.488,39.497) ; 94.193,39.792 cw(c93.897,39.497) 94.315,39.497 ccw(c93.897,39.497) 94.193,39.792 ; 94.193,39.792 ccw(c94.488,40.088) 94.488,39.67 cw(c94.488,40.088) 94.193,39.792
NetR43_1: R43.1 S1.1 U12.3 | length 18.1
  Top Layer w0.254: R43.1@56.007,100.711 57.917,100.711 58.628,101.422 60.175,101.422 U12.3@61.031,100.566 64.071,103.606 S1.1@64.071,105.283 ; 57.233,100.711 cw(c57.233,101.937) 56.366,101.07 ccw(c57.233,101.937) 57.233,100.711 ; 57.233,100.711 ccw(c57.233,99.485) 56.366,100.352 cw(c57.233,99.485) 57.233,100.711 ; U12.3@61.031,100.914 ccw(c61.031,101.754) 61.625,101.16 cw(c61.031,101.754) U12.3@61.031,100.914 ; U12.3@61.031,100.914 cw(c61.031,101.754) 60.437,101.16 ccw(c61.031,101.754) U12.3@61.031,100.914
NetR46_1: R46.1 U13.22 U13.28 | length 25.9
  Bottom Layer w0.254: R46.1@39.116,48.26 39.729,48.26 U13.28@42.87,45.119 44.035,45.119 44.45,44.704 44.45,41.988 43.775,41.313 42.964,41.313 U13.22@42.87,41.219 ; R46.1@39.243,47.752 cw(c39.243,45.352) 40.94,47.049 ccw(c39.243,45.352) R46.1@39.243,47.752 ; R46.1@39.243,48.006 cw(c39.243,46.219) 40.506,47.483 ccw(c39.243,46.219) R46.1@39.243,48.006 ; R46.1@39.243,48.26 cw(c39.243,47.087) 40.073,47.916 ccw(c39.243,47.087) R46.1@39.243,48.26 ; 41.636,46.353 cw(c40.402,45.119) 42.147,45.119 ccw(c40.402,45.119) 41.636,46.353 ; 42.069,45.92 cw(c41.269,45.119) 42.401,45.119 ccw(c41.269,45.119) 42.069,45.92 ; 42.503,45.486 cw(c42.136,45.119) 42.655,45.119 ccw(c42.136,45.119) 42.503,45.486 ; U13.22@43.545,41.267 ccw(c43.545,41.712) 43.86,41.397 cw(c43.545,41.712) U13.22@43.545,41.267
NetR47_2: R47.2 R51.2 U13.25 | length 19.6
  Bottom Layer w0.254: R47.2@39.116,45.847 R51.2@39.116,43.307 39.254,43.169 U13.25@42.87,43.169 ; 39.116,44.533 cw(c37.89,44.533) 38.757,43.666 ccw(c37.89,44.533) 39.116,44.533 ; 39.116,44.533 ccw(c40.342,44.533) 39.475,43.666 cw(c40.342,44.533) 39.116,44.533 ; 39.116,44.621 cw(c40.342,44.621) 39.475,45.488 ccw(c40.342,44.621) 39.116,44.621 ; 39.116,44.621 ccw(c37.89,44.621) 38.757,45.488 cw(c37.89,44.621) 39.116,44.621 ; R51.2@39.423,43.487 ccw(c40.189,44.253) 40.189,43.169 cw(c40.189,44.253) R51.2@39.423,43.487 ; R51.2@39.602,42.948 cw(c40.136,42.414) 40.136,43.169 ccw(c40.136,42.414) R51.2@39.602,42.948 ; R51.2@39.602,43.666 ccw(c40.803,44.867) 40.803,43.169 cw(c40.803,44.867) R51.2@39.602,43.666
NetRP2_1: RP2.1 U7.10 | length 5.6
  Top Layer w0.254: U7.10@94.109,64.489 95.15,64.489 97.155,62.484 RP2.1@97.917,62.484 ; 97.47,62.484 cw(c97.47,62.187) 97.68,62.397 ccw(c97.47,62.187) 97.47,62.484 ; 97.47,62.484 ccw(c97.47,62.781) 97.68,62.571 cw(c97.47,62.781) 97.47,62.484
NetRP2_2: RP2.2 U7.7 | length 5.3
  Top Layer w0.254: U7.7@94.109,62.989 95.634,62.989 97.028,61.595 RP2.2@97.917,61.595 ; 97.47,61.595 cw(c97.47,61.298) 97.68,61.508 ccw(c97.47,61.298) 97.47,61.595 ; 97.47,61.595 ccw(c97.47,61.892) 97.68,61.682 cw(c97.47,61.892) 97.47,61.595
NetRP2_3: RP2.3 U7.6 | length 5.5
  Top Layer w0.254: U7.6@94.109,62.489 95.499,62.489 97.282,60.706 RP2.3@97.917,60.706 ; 97.47,60.706 cw(c97.47,60.409) 97.68,60.619 ccw(c97.47,60.409) 97.47,60.706 ; 97.47,60.706 ccw(c97.47,61.003) 97.68,60.793 cw(c97.47,61.003) 97.47,60.706
NetRP2_4: RP2.4 U7.5 | length 8.3
  Top Layer w0.254: U7.5@94.109,61.989 95.237,61.989 97.409,59.817 RP2.4@97.917,59.817 ; 97.47,59.817 cw(c97.47,59.52) 97.68,59.73 ccw(c97.47,59.52) 97.47,59.817 ; 97.47,59.817 ccw(c97.47,60.114) 97.68,59.904 cw(c97.47,60.114) 97.47,59.817 ; 96.946,60.28 ccw(c97.767,61.101) 97.767,59.94 cw(c97.767,61.101) 96.946,60.28 ; 97.379,59.847 ccw(c97.767,60.234) 97.767,59.686 cw(c97.767,60.234) 97.379,59.847
NetRP4_1: RP4.1 U7.17 | length 5.3
  Top Layer w0.254: U7.17@94.109,67.989 95.206,67.989 96.647,66.548 RP4.1@97.917,66.548 ; 97.47,66.548 cw(c97.47,66.251) 97.68,66.461 ccw(c97.47,66.251) 97.47,66.548 ; 97.47,66.548 ccw(c97.47,66.845) 97.68,66.635 cw(c97.47,66.845) 97.47,66.548
NetRP4_2: RP4.2 U7.13 | length 4.9
  Top Layer w0.254: U7.13@94.109,65.989 96.317,65.989 96.647,65.659 RP4.2@97.917,65.659 ; 97.47,65.659 cw(c97.47,65.362) 97.68,65.572 ccw(c97.47,65.362) 97.47,65.659 ; 97.47,65.659 ccw(c97.47,65.956) 97.68,65.746 cw(c97.47,65.956) 97.47,65.659
NetRP4_3: RP4.3 U7.12 | length 5
  Top Layer w0.254: U7.12@94.109,65.489 95.801,65.489 96.52,64.77 RP4.3@97.917,64.77 ; 97.47,64.77 cw(c97.47,64.473) 97.68,64.683 ccw(c97.47,64.473) 97.47,64.77 ; 97.47,64.77 ccw(c97.47,65.067) 97.68,64.857 cw(c97.47,65.067) 97.47,64.77
NetRP4_4: RP4.4 U7.11 | length 5.2
  Top Layer w0.254: U7.11@94.109,64.989 95.412,64.989 96.52,63.881 RP4.4@97.917,63.881 ; 97.47,63.881 cw(c97.47,63.584) 97.68,63.794 ccw(c97.47,63.584) 97.47,63.881 ; 97.47,63.881 ccw(c97.47,64.178) 97.68,63.968 cw(c97.47,64.178) 97.47,63.881
NetU8_6: U8.6 U9.3 | length 7.2
  Top Layer w0.254: U9.3@64.343,35.941 65.532,35.941 67.31,37.719 U8.6@68.143,37.719 ; 65.311,35.941 cw(c65.311,36.359) 65.015,36.063 ccw(c65.311,36.359) 65.311,35.941 ; 65.311,35.941 ccw(c65.311,35.523) 65.015,35.819 cw(c65.311,35.523) 65.311,35.941 ; 67.35,37.719 cw(c67.35,37.301) 67.646,37.597 ccw(c67.35,37.301) 67.35,37.719 ; 67.35,37.719 ccw(c67.35,38.137) 67.646,37.841 cw(c67.35,38.137) 67.35,37.719
NetU8_7: U8.7 U9.2 | length 7.2
  Top Layer w0.254: U9.2@64.343,34.671 65.532,34.671 67.31,36.449 U8.7@68.143,36.449 ; 65.311,34.671 cw(c65.311,35.089) 65.015,34.793 ccw(c65.311,35.089) 65.311,34.671 ; 65.311,34.671 ccw(c65.311,34.253) 65.015,34.549 cw(c65.311,34.253) 65.311,34.671 ; 67.35,36.449 cw(c67.35,36.031) 67.646,36.327 ccw(c67.35,36.031) 67.35,36.449 ; 67.35,36.449 ccw(c67.35,36.867) 67.646,36.571 cw(c67.35,36.867) 67.35,36.449
NetU10_6: U10.6 U11.1 | length 9.2
  Top Layer w0.254: U10.6@84.638,36.195 85.598,36.195 86.677,37.274 86.677,38.291 v1(86.995,38.608) U11.1@88.336,38.608 ; 85.431,36.195 cw(c85.431,36.613) 85.135,36.317 ccw(c85.431,36.613) 85.431,36.195 ; 85.431,36.195 ccw(c85.431,35.777) 85.135,36.073 cw(c85.431,35.777) 85.431,36.195 ; 87.413,38.608 cw(c87.413,39.026) 87.117,38.73 ccw(c87.413,39.026) 87.413,38.608 ; 87.413,38.608 ccw(c87.413,38.19) 87.117,38.486 cw(c87.413,38.19) 87.413,38.608 ; 87.543,38.608 cw(c87.543,38.19) 87.839,38.486 ccw(c87.543,38.19) 87.543,38.608 ; 87.543,38.608 ccw(c87.543,39.026) 87.839,38.73 cw(c87.543,39.026) 87.543,38.608
NetU10_7: U10.7 U11.4 | length 12.8
  Top Layer w0.254: U10.7@84.638,37.465 v1@85.852,37.465 ; v1(86.868,34.544) 87.122,34.798 U11.4@88.336,34.798 ; 85.431,37.465 cw(c85.431,37.883) 85.135,37.587 ccw(c85.431,37.883) 85.431,37.465 ; 85.431,37.465 ccw(c85.431,37.047) 85.135,37.343 cw(c85.431,37.047) 85.431,37.465 ; 87.543,34.798 cw(c87.543,34.38) 87.839,34.676 ccw(c87.543,34.38) 87.543,34.798 ; 87.543,34.798 ccw(c87.543,35.216) 87.839,34.92 cw(c87.543,35.216) 87.543,34.798 ; U10.7@85.255,37.465 ccw(c85.255,38.316) 85.857,37.714 cw(c85.255,38.316) U10.7@85.255,37.465
  Bottom Layer w0.254: v1(85.979,37.592) 85.979,35.433 v1(86.868,34.544) ; 85.979,37.174 cw(c86.397,37.174) 86.101,37.47 ccw(c86.397,37.174) 85.979,37.174 ; 85.979,37.174 ccw(c85.561,37.174) 85.857,37.47 cw(c85.561,37.174) 85.979,37.174 ; 86.573,34.839 cw(c86.277,34.544) 86.695,34.544 ccw(c86.277,34.544) 86.573,34.839 ; 86.573,34.839 ccw(c86.868,35.135) 86.868,34.717 cw(c86.868,35.135) 86.573,34.839
NFAULT: J1.8 R55.1 R57.1 U7.21 | length 20.1
  Top Layer w0.254: U7.21@94.109,69.989 95.377,69.989 ; 95.085,69.989 98.072,69.989 104.775,63.286 J1.8@104.775,63.246
  Bottom Layer w0.254: R55.1@100.965,65.405 R57.1@100.965,62.992 104.521,62.992 J1.8@104.775,63.246
NSCS: J1.12 U7.63 | length 41.9
  Top Layer w0.254: v1(83.058,85.09) 83.284,84.864 U7.63@83.284,83.314
  Bottom Layer w0.254: v1(83.058,85.09) 83.058,85.016 88.318,79.756 90.709,79.756 93.472,76.993 93.472,69.088 94.234,68.326 103.123,68.326 104.291,69.494 105.308,69.494 106.045,70.231 106.045,72.136 J1.12@104.775,73.406 ; v1@83.231,85.09 ccw(c83.827,85.09) 83.406,84.668 cw(c83.827,85.09) v1@83.231,85.09
PVDD: 
PWRGD: J3.1 U7.24 | length 17.7
  Top Layer w0.254: U7.24@94.109,71.489 v1@95.643,71.489 ; v1(98.171,73.067) 101.896,73.067 J3.1@104.775,75.946 ; 98.589,73.067 cw(c98.589,73.484) 98.293,73.189 ccw(c98.589,73.484) 98.589,73.067 ; 98.589,73.067 ccw(c98.589,72.649) 98.293,72.944 cw(c98.589,72.649) 98.589,73.067 ; 95.063,71.489 cw(c95.063,70.679) 95.636,71.252 ccw(c95.063,70.679) 95.063,71.489
  Bottom Layer w0.254: v1(95.758,71.374) 97.451,73.067 v1(98.171,73.067) ; 96.053,71.669 cw(c95.758,71.965) 95.758,71.547 ccw(c95.758,71.965) 96.053,71.669 ; 96.053,71.669 ccw(c96.349,71.374) 95.931,71.374 cw(c96.349,71.374) 96.053,71.669 ; 97.753,73.067 cw(c97.753,72.649) 98.049,72.944 ccw(c97.753,72.649) 97.753,73.067 ; 97.753,73.067 ccw(c97.753,73.484) 98.049,73.189 cw(c97.753,73.484) 97.753,73.067
REFM: C50.1 U7.55 | length 5.3
  Top Layer w0.254: U7.55@87.284,83.314 87.284,86.649 87.884,87.249 C50.1@87.884,88.392
REFP: C51.1 U7.56 | length 5.7
  Top Layer w0.254: C51.1@85.344,88.392 86.784,86.952 U7.56@86.784,83.314
RESET: C53.2 R35.1 U7.80 U12.2 | length 25.4
  Top Layer w0.254: U12.2@61.031,98.316 C53.2@63.518,98.316 ; C53.2@64.135,98.933 R35.1@66.421,98.933 66.421,95.631 74.784,87.268 U7.80@74.784,83.314 ; 61.509,98.316 cw(c61.509,98.794) 61.171,98.456 ccw(c61.509,98.794) 61.509,98.316 ; 61.509,98.316 ccw(c61.509,97.838) 61.171,98.176 cw(c61.509,97.838) 61.509,98.316
RESEXT: R34.2 U7.57 | length 7.1
  Top Layer w0.254: R34.2@82.804,88.392 84.455,86.741 85.471,86.741 86.284,85.928 U7.57@86.284,83.314
SA: D9.1 J13.2 R48.1 R52.1 | length 24.3
  Top Layer w0.254: D9.1@73.618,99.329 75.311,97.636 R52.1@75.311,97.282 R48.1@77.851,97.282 ; D9.1@73.618,99.568 73.618,101.05 J13.2@76.581,104.013 ; 73.618,100.227 cw(c72.959,100.227) 73.425,99.761 ccw(c72.959,100.227) 73.618,100.227 ; 73.618,100.227 ccw(c74.277,100.227) 73.811,99.761 cw(c74.277,100.227) 73.618,100.227 ; 75.091,102.523 cw(c76.581,101.032) 76.581,103.14 ccw(c76.581,101.032) 75.091,102.523 ; 75.091,102.523 ccw(c73.6,104.013) 75.708,104.013 cw(c73.6,104.013) 75.091,102.523 ; 75.524,102.956 cw(c76.581,101.9) 76.581,103.394 ccw(c76.581,101.9) 75.524,102.956 ; 75.524,102.956 ccw(c74.468,104.013) 75.962,104.013 cw(c74.468,104.013) 75.524,102.956
SB: D10.1 J13.3 R49.1 R53.1 | length 13.3
  Top Layer w0.254: J13.3@81.661,104.013 81.661,102.008 83.862,99.807 83.862,99.329 82.931,98.398 ; R49.1@85.471,97.282 R53.1@82.931,97.282 82.931,98.398 ; 82.931,98.398 cw(c82.222,98.398) 82.635,97.822 ccw(c82.222,98.398) 82.931,98.398 ; 82.931,98.398 ccw(c83.64,98.398) 83.227,97.822 cw(c83.64,98.398) 82.931,98.398
SC: D11.1 J13.4 R50.1 R54.1 | length 12.8
  Top Layer w0.254: J13.4@86.741,104.013 90.382,100.372 D11.1@90.382,99.568 ; D11.1@90.297,99.483 R54.1@90.297,97.282 R50.1@92.837,97.282 ; 90.382,100.227 cw(c89.723,100.227) 90.189,99.761 ccw(c89.723,100.227) 90.382,100.227 ; 90.382,100.227 ccw(c91.041,100.227) 90.575,99.761 cw(c91.041,100.227) 90.382,100.227
SCI-RXA: U7.141 U8.2 | length 29.6
  Top Layer w0.254: U8.2@73.843,36.449 74.432,37.038 ; U7.141@74.784,58.164 v1(74.784,56.28) 74.784,54.756 76.581,52.959 76.581,37.899 75.72,37.038 74.432,37.038 ; 74.432,37.038 ccw(c74.725,36.745) 74.367,36.536 cw(c74.725,36.745) 74.432,37.038 ; 74.784,55.862 cw(c75.202,55.862) 74.906,56.158 ccw(c75.202,55.862) 74.784,55.862 ; 74.784,55.862 ccw(c74.366,55.862) 74.662,56.158 cw(c74.366,55.862) 74.784,55.862 ; 74.784,56.698 cw(c74.366,56.698) 74.662,56.402 ccw(c74.366,56.698) 74.784,56.698 ; 74.784,56.698 ccw(c75.202,56.698) 74.906,56.402 cw(c75.202,56.698) 74.784,56.698 ; U8.2@73.929,36.28 cw(c74.137,36.402) 73.967,36.573 ccw(c74.137,36.402) U8.2@73.929,36.28 ; U8.2@74.148,36.408 cw(c74.431,36.574) 74.199,36.805 ccw(c74.431,36.574) U8.2@74.148,36.408
SCI-TXA: U7.2 U8.3 | length 70.2
  Top Layer w0.254: U8.3@73.843,37.719 v1(75.438,37.719) ; U7.2@94.109,60.489 95.086,60.489 v1(96.774,58.801) ; 74.636,37.719 cw(c74.636,38.137) 74.34,37.841 ccw(c74.636,38.137) 74.636,37.719 ; 74.636,37.719 ccw(c74.636,37.301) 74.34,37.597 cw(c74.636,37.301) 74.636,37.719 ; 75.02,37.719 cw(c75.02,37.301) 75.316,37.597 ccw(c75.02,37.301) 75.02,37.719 ; 75.02,37.719 ccw(c75.02,38.137) 75.316,37.841 cw(c75.02,38.137) 75.02,37.719 ; 96.479,59.096 cw(c96.183,58.801) 96.601,58.801 ccw(c96.183,58.801) 96.479,59.096 ; 96.479,59.096 ccw(c96.774,59.392) 96.774,58.974 cw(c96.774,59.392) 96.479,59.096
  Bottom Layer w0.254: v1(75.438,37.719) 75.438,35.687 78.645,32.48 101.854,32.48 102.473,33.099 102.473,53.102 v1(96.774,58.801) ; 75.438,37.301 cw(c75.856,37.301) 75.56,37.597 ccw(c75.856,37.301) 75.438,37.301 ; 75.438,37.301 ccw(c75.02,37.301) 75.316,37.597 cw(c75.02,37.301) 75.438,37.301 ; 97.069,58.506 cw(c97.365,58.801) 96.947,58.801 ccw(c97.365,58.801) 97.069,58.506 ; 97.069,58.506 ccw(c96.774,58.21) 96.774,58.628 cw(c96.774,58.21) 97.069,58.506
SCLK: J1.11 U7.62 | length 34.1
  Top Layer w0.254: U7.62@83.784,83.314 83.784,84.927 v1(83.947,85.09)
  Bottom Layer w0.254: v1(83.947,85.09) 88.773,80.264 90.919,80.264 93.98,77.203 93.98,70.866 94.615,70.231 104.14,70.231 J1.11@104.775,70.866 ; 84.242,84.795 cw(c84.538,85.09) 84.12,85.09 ccw(c84.538,85.09) 84.242,84.795 ; 84.242,84.795 ccw(c83.947,84.499) 83.947,84.917 cw(c83.947,84.499) 84.242,84.795
SDI: J1.9 U7.27 | length 13.6
  Top Layer w0.254: U7.27@94.109,72.989 96.175,72.989 103.378,65.786 J1.9@104.775,65.786
SDO: J1.10 U7.28 | length 12.8
  Top Layer w0.254: U7.28@94.109,73.489 96.818,73.489 97.49,72.817 97.49,72.785 101.949,68.326 J1.10@104.775,68.326
SHA: 
SHB: 
SHC: 
SLA: 
SLB: 
SLC: 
